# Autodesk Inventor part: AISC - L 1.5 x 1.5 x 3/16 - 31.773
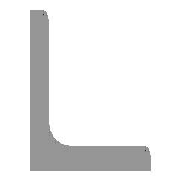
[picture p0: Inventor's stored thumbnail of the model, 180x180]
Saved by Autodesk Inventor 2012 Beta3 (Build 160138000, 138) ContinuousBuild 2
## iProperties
_CCFamilyMember: 5
_CCFamilyDisplayName: ANSI L (Equal angles) - Angle Steel
_FrameMemberDoc: Frame Member File
_Version: 15.0.0
_GetPNFromCC: 1
Created: 2010-11
Part Number: AISC - L 1.5 x 1.5 x 3/16 - 31.773
Material: Steel, Mild
Description: Angle Steel
Document SubType Name: Modeling
Standard: ANSI
Designer: Beta-8540w
Standards Organization: ANSI
Language: en-US
Size Designation: L 1.5 x 1.5 x 3/16
Categories: <MemberInstance><Categories><Category DisplayName="Structural Shapes" InternalName="089c4875-fa83-4c05-b084-43b9cc11f5ed" Mnemonic="GRDR"><CategoryParameter Dis
Stock Number: L 1.5 x 1.5 x 3/16
Density: 7.86 g/cm^3
IsCustomPart: 1
G_L: 31.773 in
G_W: 1.500 in
G_H: 1.500 in
+EC3E699C-0520-4E89-B4DB-B1DFE966D730+CUTDETAIL1: Cut
Author: Beta-8540w
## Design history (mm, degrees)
node "Start plane"
node "End plane"
sketch "Sketch"
  geometry: L1 (38.1, 0)-(0, 0); L2 (0, 0)-(0, 38.1); L3 (0, 38.1)-(2.476, 38.1); L4 (4.762, 35.814)-(4.762, 9.589); L5 (9.588, 4.763)-(35.814, 4.763); L6 (38.1, 2.477)-(38.1, 0); L7 (0, -11.041)-(0, 31.538); L8 (-11.041, 0)-(31.538, 0); L9 (0, 48.496)-(0, -20.964) reference; L10 (-20.964, 0)-(48.496, 0) reference; A1 r 4.826 centre (9.588, 9.589) between (4.762, 9.589) and (9.588, 4.763); A2 r 2.286 centre (2.476, 35.814) between (4.762, 35.814) and (2.476, 38.1); A3 r 2.286 centre (35.814, 2.477) between (38.1, 2.477) and (35.814, 4.763); 3 further points
  constraints: 16 end point, 6 point on circle, 6 point on line, 6 tangent, 4 parallel, 3 centre point, 2 collinear, 1 equal radius, 1 horizontal, 1 perpendicular
  dimensions: "d0" = 38.1 distance between parallel lines of L6 L2 (= G_H); "d1" = 38.1 distance between parallel lines of L3 L1 (= G_H); "d2" = 4.7625 distance between parallel lines of L2 L4 (= G_T); "d3" = 4.7625 distance between parallel lines of L1 L5 (= G_T); "d10" = 0 distance between parallel lines of L7 L2 (computed from ex); "d11" = 0 distance between parallel lines of L8 L1 (computed from d10); "d14" = 4.826 radius of A1 (= G_IR); "d15" = 2.286 radius of A2 (= G_ER)
extrude "Body" new body sketch "Sketch" stored distance "d4" = 807.0404 (= G_L); taper "d5" = 0 deg
node "Driven Length"
  sketch "Sketch3"
    geometry: L1 (0, 0)-(10, 0) reference
    constraints: 2 end point, 1 horizontal
  workplane "Work Plane3"
  sketch "Sketch4"
    geometry: L1 (-2, 0)-(12, 0) reference; L2 (-2, 807.04)-(12, 807.04) reference
    dimensions: "d17" = 807.0404 distance between parallel lines of L1 L2 (derived)
workplane "Work Plane4"
split "Split1"
body "Solid1"
other parameters: "G_H" = 38.1 [user parameter; used in 2 equation terms], "G_T" = 4.7625 [user parameter; used in 2 equation terms], "G_ER" = 2.286 [user parameter; used in 1 equation term], "G_IR" = 4.826 [user parameter; used in 1 equation term], "G_L" = 807.0404 (= d17) [user parameter; used in 1 equation term], "ex" = 0 [user parameter; used in 1 equation term], "G_OFFSET_START" = 0 [user parameter; used in 1 equation term], "G_OFFSET_END" = -29.72503 [user parameter; used in 1 equation term], "d12" = 0 (computed from G_OFFSET_START), "d13" = 807.0404 (= G_OFFSET_END + B_L), "B_L" = 836.76542 [user parameter; used in 1 equation term], "d16" = 90 deg, "MAS" = 0.26787 [user parameter]
